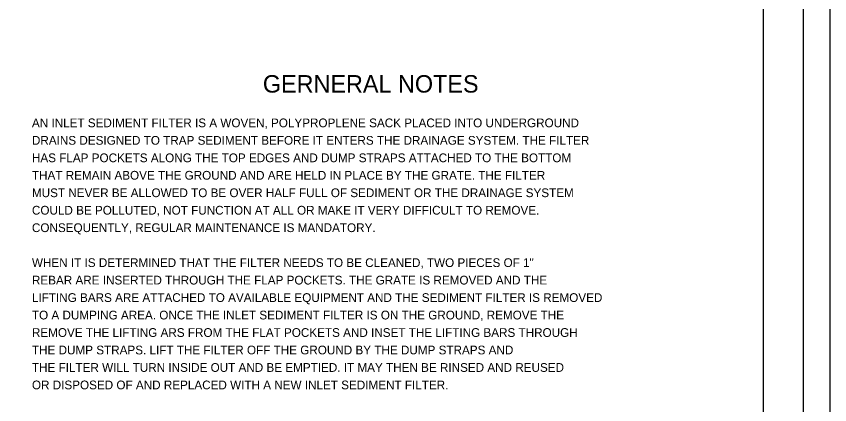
# Model space of a CAD drawing. Extents: x -120.7 to -50.3, y -20.2 to 3.8.
# Drawn here: x -61.42 to -50.26, y -9.93 to -4.59 of the extents above; entities that cross this region are included whole.
import ezdxf

# ---------------------------------------------------------------- set-up
doc = ezdxf.new("R2010")
doc.units = 0
for name, color, linetype in [('SHT_Plot_Shape_Full', 7, 'Continuous'), ('SHT_Plot_Shape_Half', 7, 'Continuous'), ('SHT_Sheet_Border', 7, 'Continuous'), ('TYP_Typical_Section_Txt', 7, 'Continuous')]:
    doc.layers.add(name, color=color, linetype=linetype)

msp = doc.modelspace()

# ---------------------------------------------------------------- linework, layer by layer
at = {"layer": 'SHT_Plot_Shape_Full'}
msp.add_lwpolyline([(-86.259, 3.759), (-50.259, 3.759), (-50.259, -20.241), (-86.259, -20.241)], close=True, dxfattribs=at)
at = {"layer": 'SHT_Plot_Shape_Half'}
msp.add_lwpolyline([(-84.622, 2.934), (-50.622, 2.934), (-50.622, -19.066), (-84.622, -19.066)], close=True, dxfattribs=at)
at = {"layer": 'SHT_Sheet_Border'}
msp.add_lwpolyline([(-51.172, -18.566), (-82.672, -18.566), (-82.672, 2.434), (-51.172, 2.434)], close=True, dxfattribs=at)

# ---------------------------------------------------------------- texts
at = {"layer": 'TYP_Typical_Section_Txt'}
for s, height, p in [('GERNERAL NOTES', 0.24, (-58.039, -5.639)), ('AN INLET SEDIMENT FILTER IS A WOVEN, POLYPROPLENE SACK PLACED INTO UNDERGROUND ', 0.12, (-61.208, -6.115)), ('DRAINS DESIGNED TO TRAP SEDIMENT BEFORE IT ENTERS THE DRAINAGE SYSTEM. THE FILTER ', 0.12, (-61.208, -6.355)), ('HAS FLAP POCKETS ALONG THE TOP EDGES AND DUMP STRAPS ATTACHED TO THE BOTTOM', 0.12, (-61.208, -6.595)), ('THAT REMAIN ABOVE THE GROUND AND ARE HELD IN PLACE BY THE GRATE. THE FILTER', 0.12, (-61.208, -6.835)), ('MUST NEVER BE ALLOWED TO BE OVER HALF FULL OF SEDIMENT OR THE DRAINAGE SYSTEM ', 0.12, (-61.208, -7.075)), ('COULD BE POLLUTED, NOT FUNCTION AT ALL OR MAKE IT VERY DIFFICULT TO REMOVE.', 0.12, (-61.208, -7.315)), ('CONSEQUENTLY, REGULAR MAINTENANCE IS MANDATORY.', 0.12, (-61.208, -7.555)), ('WHEN IT IS DETERMINED THAT THE FILTER NEEDS TO BE CLEANED, TWO PIECES OF 1"', 0.12, (-61.208, -8.035)), ('REBAR ARE INSERTED THROUGH THE FLAP POCKETS. THE GRATE IS REMOVED AND THE', 0.12, (-61.208, -8.275)), ('LIFTING BARS ARE ATTACHED TO AVAILABLE EQUIPMENT AND THE SEDIMENT FILTER IS REMOVED', 0.12, (-61.208, -8.515)), ('TO A DUMPING AREA. ONCE THE INLET SEDIMENT FILTER IS ON THE GROUND, REMOVE THE', 0.12, (-61.208, -8.755)), ('REMOVE THE LIFTING ARS FROM THE FLAT POCKETS AND INSET THE LIFTING BARS THROUGH', 0.12, (-61.208, -8.995)), ('THE DUMP STRAPS. LIFT THE FILTER OFF THE GROUND BY THE DUMP STRAPS AND', 0.12, (-61.208, -9.235)), ('THE FILTER WILL TURN INSIDE OUT AND BE EMPTIED. IT MAY THEN BE RINSED AND REUSED', 0.12, (-61.208, -9.475)), ('OR DISPOSED OF AND REPLACED WITH A NEW INLET SEDIMENT FILTER.', 0.12, (-61.208, -9.715))]:
    msp.add_text(s, height=height, dxfattribs=at).set_placement(p)

doc.saveas('drawing.dxf')
